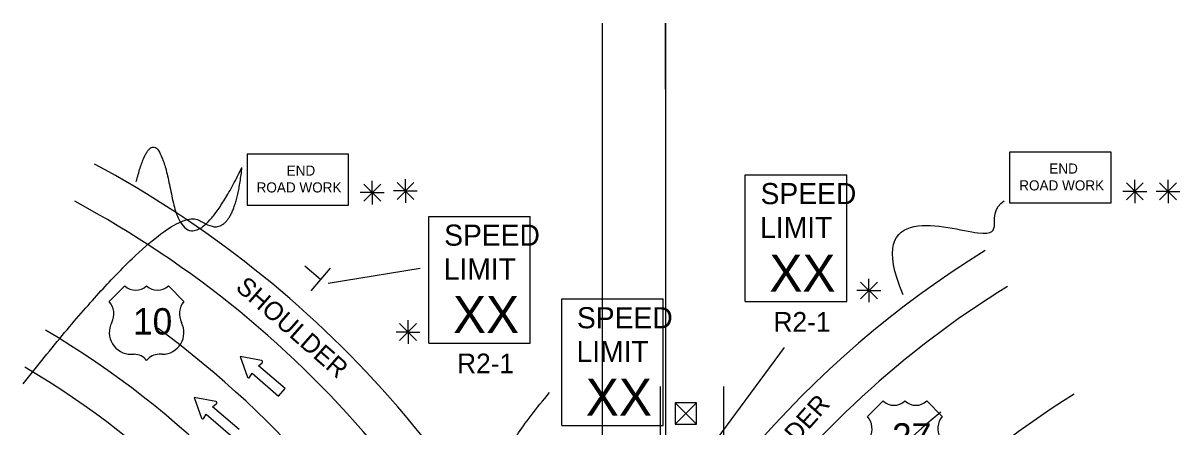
# Model space of a CAD drawing. Extents: x 16284 to 18468, y 5417 to 6974.
# Drawn here: x 16725 to 17163.1, y 6821.2 to 6974.1 of the extents above; entities that cross this region are included whole.
import ezdxf

# ---------------------------------------------------------------- set-up
doc = ezdxf.new("R2010")
doc.units = 0
for name, color, linetype in [('ALI_LEGAL_EX', 7, 'Continuous'), ('MT_SCRATCH_LEVEL_E', 7, 'Continuous'), ('PAVT_EDGE_EX', 7, 'Continuous'), ('TRAFFIC_SIGNS_PR', 7, 'Continuous'), ('TYPICAL_EX', 7, 'Continuous'), ('TYPICAL_TEXT_DIMEN_PR', 7, 'Continuous')]:
    doc.layers.add(name, color=color, linetype=linetype)

msp = doc.modelspace()

# ---------------------------------------------------------------- linework, layer by layer
at = {"layer": 'ALI_LEGAL_EX'}
for p, q in [((16944.3, 6974.12), (16944.3, 6155.98)), ((16968.3, 6974.12), (16968.3, 6155.98)), ((16966.29, 6836.53), (16966.29, 5997.6)), ((16990.29, 6836.53), (16990.29, 5997.6))]:
    msp.add_line(p, q, dxfattribs=at)
msp.add_lwpolyline([(16968.3, 6949.12), (16968.3, 6974.12)], dxfattribs=at)
for centre, radius, start, end in [((16561.13, 6564.7), 364, 0, 53.7921), ((17289.13, 6564.7), 340, 129.5666, 180)]:
    msp.add_arc(centre, radius, start, end, dxfattribs=at)
at = {"layer": 'MT_SCRATCH_LEVEL_E'}
for p, q in [((16815.35, 6846.27), (16807.16, 6847.85)), ((16807.16, 6847.85), (16809.97, 6840.01)), ((16814.16, 6844.32), (16815.56, 6845.47)), ((16824.21, 6835.68), (16814.16, 6844.32)), ((16810.8, 6839.93), (16811.72, 6841.49)), ((16811.72, 6841.49), (16821.77, 6832.84)), ((16821.77, 6832.84), (16824.21, 6835.68)), ((16797.97, 6830.75), (16789.78, 6832.33)), ((16789.78, 6832.33), (16792.59, 6824.49)), ((16796.78, 6828.8), (16798.18, 6829.94)), ((16793.42, 6824.41), (16794.34, 6825.96)), ((16794.34, 6825.96), (16804.39, 6817.32)), ((16806.83, 6820.15), (16796.78, 6828.8))]:
    msp.add_line(p, q, dxfattribs=at)
for centre, start, end in [((16815.26, 6845.82), 309.3361, 79.073), ((16810.4, 6840.18), 199.7248, 329.2637), ((16797.88, 6830.29), 309.3361, 79.073), ((16793.02, 6824.65), 199.7248, 329.2637)]:
    msp.add_arc(centre, 0.463, start, end, dxfattribs=at)
at = {"layer": 'PAVT_EDGE_EX'}
for centre, radius, start, end in [((16561.13, 6564.7), 404, 21.0961, 61.7914), ((16561.13, 6564.7), 388, 17.512, 61.7914), ((17289.13, 6564.7), 380, 121.7103, 157.5011), ((17289.13, 6564.7), 364, 121.7103, 165.0045), ((16561.13, 6564.7), 340, 0, 59.5346), ((16561.13, 6564.7), 324, 0, 59.4835), ((17289.13, 6564.7), 316, 121.7103, 180)]:
    msp.add_arc(centre, radius, start, end, dxfattribs=at)
at = {"layer": 'TRAFFIC_SIGNS_PR'}
for p, q in [((16998.53, 6916.68), (17036.93, 6916.68)), ((16998.53, 6868.68), (16998.53, 6916.68)), ((17036.93, 6868.68), (17036.93, 6916.68)), ((16878.7, 6900.93), (16917.1, 6900.93)), ((16878.7, 6852.93), (16878.7, 6900.93)), ((16917.1, 6852.93), (16917.1, 6900.93)), ((16928.99, 6869.65), (16967.39, 6869.65)), ((16928.99, 6821.65), (16928.99, 6869.65)), ((16967.39, 6821.65), (16967.39, 6869.65)), ((16998.53, 6868.68), (17036.93, 6868.68)), ((16878.7, 6852.93), (16917.1, 6852.93)), ((16928.99, 6821.65), (16967.39, 6821.65))]:
    msp.add_line(p, q, dxfattribs=at)
for points in [[(16809.82, 6905.22), (16848.22, 6905.22), (16848.22, 6924.42), (16809.82, 6924.42)], [(17098.64, 6905.99), (17137.04, 6905.99), (17137.04, 6925.19), (17098.64, 6925.19)]]:
    msp.add_lwpolyline(points, close=True, dxfattribs=at)
at = {"layer": 'TYPICAL_EX'}
for p, q in [((16757.63, 6868.72), (16763.52, 6874.62)), ((16785.93, 6868.72), (16780.03, 6874.62)), ((16765.87, 6848.66), (16767.05, 6848.66)), ((16777.68, 6848.66), (16776.5, 6848.66)), ((17044.83, 6825.12), (17050.72, 6831.02)), ((17073.13, 6825.12), (17067.23, 6831.02))]:
    msp.add_line(p, q, dxfattribs=at)
for centre, radius, start, end in [((16767.65, 6878.91), 5.96, 226.1404, 313.8596), ((16775.9, 6878.91), 5.96, 226.1404, 313.8596), ((16752.04, 6864), 7.31, 333.0977, 40.1936), ((16791.51, 6864), 7.31, 139.8064, 206.9023), ((16765.89, 6856.91), 8.24, 152.6698, 269.9013), ((16777.67, 6856.91), 8.24, 270.0987, 27.3302), ((16767.07, 6842.76), 5.91, 37.1038, 90.1385), ((16776.49, 6842.76), 5.91, 89.8615, 142.8962), ((17054.85, 6835.31), 5.96, 226.1404, 313.8596), ((17063.11, 6835.31), 5.96, 226.1404, 313.8596), ((17039.24, 6820.4), 7.31, 333.0977, 40.1936), ((17078.72, 6820.4), 7.31, 139.8064, 206.9023)]:
    msp.add_arc(centre, radius, start, end, dxfattribs=at)
at = {"layer": 'TYPICAL_TEXT_DIMEN_PR'}
for p, q in [((16854.06, 6913.1), (16860.43, 6906.72)), ((16860.43, 6913.1), (16854.06, 6906.72)), ((16857.24, 6909.91), (16857.24, 6914.36)), ((16866.61, 6913.72), (16872.99, 6907.35)), ((16872.99, 6913.72), (16866.61, 6907.35)), ((16869.8, 6910.53), (16869.8, 6914.99)), ((17142.88, 6913.56), (17149.25, 6907.18)), ((17149.25, 6913.56), (17142.88, 6907.18)), ((17146.07, 6910.37), (17146.07, 6914.82)), ((17161.81, 6913.56), (17155.43, 6907.18)), ((17155.44, 6913.56), (17161.81, 6907.18)), ((17158.62, 6910.37), (17158.62, 6914.82)), ((16857.24, 6909.91), (16852.71, 6909.91)), ((16857.24, 6909.91), (16860.43, 6909.91)), ((16857.24, 6909.91), (16861.72, 6909.91)), ((16857.24, 6909.91), (16857.24, 6905.41)), ((16869.8, 6910.53), (16865.27, 6910.53)), ((16869.8, 6910.53), (16872.99, 6910.53)), ((16869.8, 6910.53), (16874.28, 6910.53)), ((16869.8, 6910.53), (16869.8, 6906.03)), ((17146.07, 6910.37), (17141.53, 6910.37)), ((17146.07, 6910.37), (17149.25, 6910.37)), ((17146.07, 6910.37), (17150.54, 6910.37)), ((17146.07, 6910.37), (17146.07, 6905.87)), ((17158.62, 6910.37), (17154.09, 6910.37)), ((17158.62, 6910.37), (17161.81, 6910.37)), ((17158.62, 6910.37), (17163.1, 6910.37)), ((17158.62, 6910.37), (17158.62, 6905.87)), ((16837.65, 6876.99), (16831.75, 6882.07)), ((16841.32, 6881.26), (16833.98, 6872.73)), ((16840.54, 6875.67), (16875.44, 6881.26)), ((17042.16, 6876.04), (17048.54, 6869.67)), ((17048.54, 6876.04), (17042.16, 6869.67)), ((17045.35, 6872.86), (17045.35, 6877.31)), ((17045.35, 6872.86), (17040.82, 6872.86)), ((17045.35, 6872.86), (17048.54, 6872.86)), ((17045.35, 6872.86), (17049.83, 6872.86)), ((17045.35, 6872.86), (17045.35, 6868.36)), ((16870.78, 6857.09), (16870.78, 6861.55)), ((16870.78, 6857.09), (16866.25, 6857.09)), ((16867.6, 6860.28), (16873.97, 6853.9)), ((16873.97, 6860.28), (16867.6, 6853.9)), ((16870.78, 6857.09), (16873.97, 6857.09)), ((16870.78, 6857.09), (16875.26, 6857.09)), ((16870.78, 6857.09), (16870.78, 6852.59)), ((16957.13, 6775.18), (17013.42, 6851.3)), ((16972, 6822.26), (16980, 6830.26)), ((16972, 6830.25), (16980, 6822.26))]:
    msp.add_line(p, q, dxfattribs=at)
msp.add_lwpolyline([(16972, 6830.25), (16972, 6822.26), (16980, 6822.26), (16980, 6830.26)], close=True, dxfattribs=at)
for points, degree in [([(16767.86, 6914.07), (16775.05, 6942.33), (16787.12, 6877), (16807.9, 6919.45)], 2), ([(16725.01, 6837.52), (16780.55, 6907.8), (16804.75, 6890.22), (16807.9, 6919.45)], 2), ([(17058.28, 6871.13), (17043.1, 6907.35), (17107.34, 6885.02), (17088.67, 6901.32), (17096.57, 6906.83)], 3), ([(16909.99, 6783.05), (16925.05, 6790.93), (16915.89, 6798.15), (16900.83, 6806.02), (16924.4, 6834.24)], 2)]:
    msp.add_open_spline(points, degree=degree, dxfattribs=at)

# ---------------------------------------------------------------- texts
at = {"layer": 'TRAFFIC_SIGNS_PR'}
for s, height, p in [('END', 3.831, (16824.82, 6916.35)), ('END', 3.831, (17113.65, 6917.12)), ('ROAD WORK', 3.831, (16813.43, 6909.97)), ('SPEED', 8, (17004.3, 6905.54)), ('ROAD WORK', 3.831, (17102.26, 6910.74)), ('LIMIT', 8, (17004.14, 6892.74)), ('SPEED', 8, (16884.47, 6889.8)), ('LIMIT', 8, (16884.31, 6876.99)), ('XX', 14.031, (17007.64, 6872.43)), ('XX', 14.031, (16887.82, 6856.69)), ('SPEED', 8, (16934.76, 6858.52)), ('R2-1', 7.44, (17009.21, 6857.24)), ('LIMIT', 8, (16934.6, 6845.72)), ('R2-1', 7.44, (16889.38, 6841.49)), ('XX', 14.031, (16938.11, 6825.41))]:
    msp.add_text(s, height=height, dxfattribs=at).set_placement(p)
at = {"layer": 'TYPICAL_EX'}
for s, p in [('10', (16766.62, 6856.15)), ('27', (17054.09, 6812.55))]:
    msp.add_text(s, height=10, dxfattribs=at).set_placement(p)
at = {"layer": 'TYPICAL_TEXT_DIMEN_PR'}
for rotation, p in [(318.763, (16805.09, 6873.43)), (48.378, (16996.49, 6790.64))]:
    msp.add_text('SHOULDER', height=7, rotation=rotation, dxfattribs=at).set_placement(p)

doc.saveas('drawing.dxf')
